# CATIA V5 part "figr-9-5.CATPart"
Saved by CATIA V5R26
Part number: Part1
Bounding box of the stored display mesh (mm): x -71.324 to 69.61, y -211.059 to 0, z 0 to 45
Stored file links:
  D:\_Deepak\CATIA\CATIA V5-6R2016_Deepak\Resources\Part files\Partfiles\c09_catia_v5_6r2016_prt\figr-9-5.CATPart
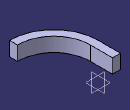
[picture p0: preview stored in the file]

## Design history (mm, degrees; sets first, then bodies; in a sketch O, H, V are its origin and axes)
Body1 (main body)
  Sketch1 on xy-plane, origin (0, 0, 0), H (1, 0, 0), V (0, 1, 0)
    line L1 (0, 0) -> (0, -70.1255)
    arc A1 centre (69.6095, -70.1255) radius 69.6095 from (0, -70.1255) to (69.6095, -139.7351) ccw
    vertical: L1 V
    tangency: A1 L1
  Sketch2 on zx-plane, origin (0, 0, 0), H (-1, 0, 0), V (0, 0, 1)
    point P1 (46.3244, 0)
    line L1 (46.3244, 0) -> (71.3244, 0)
    line L2 (71.3244, 0) -> (71.3244, 45)
    line L3 (71.3244, 45) -> (46.3244, 45)
    line L4 (46.3244, 45) -> (46.3244, 0)
    length L3 = 25
    length L2 = 45
    coincidence: P1 H
    horizontal: L1 H, L3 H
    vertical: L2 V, L4 V
  Rib1: profile Sketch2, centre curve Sketch1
